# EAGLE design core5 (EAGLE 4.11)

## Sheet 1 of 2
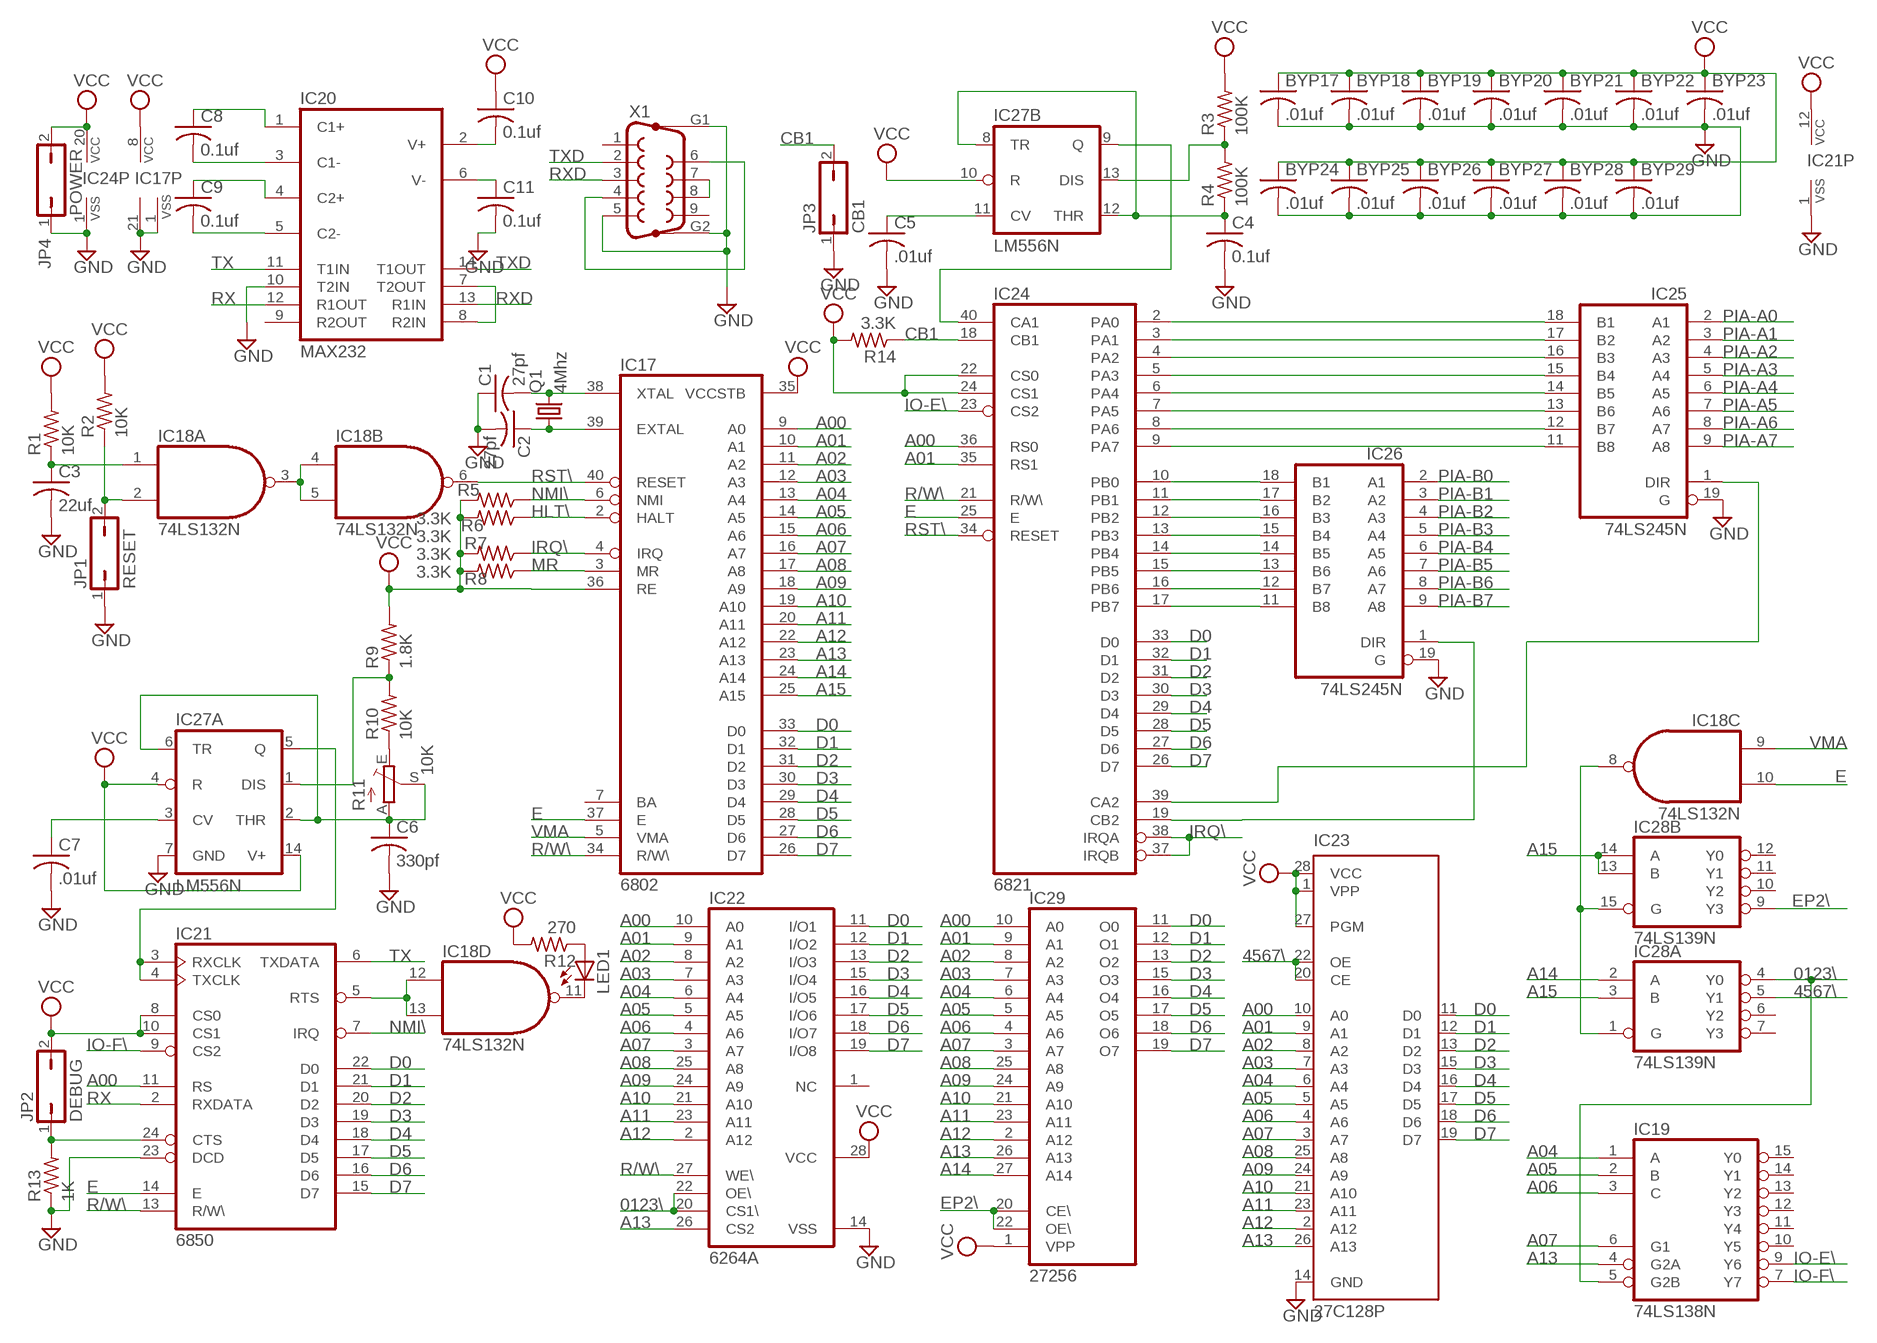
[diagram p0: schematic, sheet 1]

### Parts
BYP17  .01uf  C-US050-025X075  [C050-025X075]
BYP18  .01uf  C-US050-025X075  [C050-025X075]
BYP19  .01uf  C-US050-025X075  [C050-025X075]
BYP20  .01uf  C-US050-025X075  [C050-025X075]
BYP21  .01uf  C-US050-025X075  [C050-025X075]
BYP22  .01uf  C-US050-025X075  [C050-025X075]
BYP23  .01uf  C-US050-025X075  [C050-025X075]
BYP24  .01uf  C-US050-025X075  [C050-025X075]
BYP25  .01uf  C-US050-025X075  [C050-025X075]
BYP26  .01uf  C-US050-025X075  [C050-025X075]
BYP27  .01uf  C-US050-025X075  [C050-025X075]
BYP28  .01uf  C-US050-025X075  [C050-025X075]
BYP29  .01uf  C-US050-025X075  [C050-025X075]
C1  27pf  C-US050-025X075  [C050-025X075]
C2  27pf  C-US050-025X075  [C050-025X075]
C3  22uf  C-US102-043X133  [C102-043X133]
C4  0.1uf  C-US050-025X075  [C050-025X075]
C5  .01uf  C-US050-025X075  [C050-025X075]
C6  330pf  C-US050-025X075  [C050-025X075]
C7  .01uf  C-US050-025X075  [C050-025X075]
C8  0.1uf  C-US050-025X075  [C050-025X075]
C9  0.1uf  C-US050-025X075  [C050-025X075]
C10  0.1uf  C-US050-025X075  [C050-025X075]
C11  0.1uf  C-US050-025X075  [C050-025X075]
IC17  6802  [DIL40]
IC18  74LS132N  74LS00N  [DIL14]
IC19  74LS138N  [DIL16]
IC20  MAX232  [DIL16]
IC21  6850  [DIL24]
IC22  6264A  [DIL28-6]
IC23  27C128P  [DIL28-6]
IC24  6821  [DIL40]
IC25  74LS245N  [DIL20]
IC26  74LS245N  [DIL20]
IC27  LM556N  [DIL14]
IC28  74LS139N  [DIL16]
IC29  27256  [DIL28]
JP1  RESET  JP1Q  [JP1]
JP2  DEBUG  JP1Q  [JP1]
JP3  CB1  JP1Q  [JP1]
JP4  POWER  JP1Q  [JP1]
LED1  LED3MM  [LED3MM]
Q1  4Mhz  CRYTALHC18U-V  [HC18U-V]
R1  10K  R-US_0207/7  [0207/7]
R2  10K  R-US_0207/7  [0207/7]
R3  100K  R-US_0207/7  [0207/7]
R4  100K  R-US_0207/7  [0207/7]
R5  3.3K  R-US_0207/7  [0207/7]
R6  3.3K  R-US_0207/7  [0207/7]
R7  3.3K  R-US_0207/7  [0207/7]
R8  3.3K  R-US_0207/7  [0207/7]
R9  1.8K  R-US_0207/7  [0207/7]
R10  10K  R-US_0207/7  [0207/7]
R11  10K  TRIM_EU-B90P  [SP19L]
R12  270  R-US_0207/7  [0207/7]
R13  1K  R-US_0207/7  [0207/7]
R14  3.3K  R-US_0207/7  [0207/7]
X1  F09HP  [F09HP]

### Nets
0123\: IC19.5(G2B) IC22.20(CS1\) IC22.22(OE\) IC28.4(A:Y0)
4567\: IC23.20(CE) IC23.22(OE) IC28.5(A:Y1)
A00: IC17.9(A0) IC21.11(RS) IC22.10(A0) IC23.10(A0) IC24.36(RS0) IC29.10(A0)
A01: IC17.10(A1) IC22.9(A1) IC23.9(A1) IC24.35(RS1) IC29.9(A1)
A02: IC17.11(A2) IC22.8(A2) IC23.8(A2) IC29.8(A2)
A03: IC17.12(A3) IC22.7(A3) IC23.7(A3) IC29.7(A3)
A04: IC17.13(A4) IC19.1(A) IC22.6(A4) IC23.6(A4) IC29.6(A4)
A05: IC17.14(A5) IC19.2(B) IC22.5(A5) IC23.5(A5) IC29.5(A5)
A06: IC17.15(A6) IC19.3(C) IC22.4(A6) IC23.4(A6) IC29.4(A6)
A07: IC17.16(A7) IC19.6(G1) IC22.3(A7) IC23.3(A7) IC29.3(A7)
A08: IC17.17(A8) IC22.25(A8) IC23.25(A8) IC29.25(A8)
A09: IC17.18(A9) IC22.24(A9) IC23.24(A9) IC29.24(A9)
A10: IC17.19(A10) IC22.21(A10) IC23.21(A10) IC29.21(A10)
A11: IC17.20(A11) IC22.23(A11) IC23.23(A11) IC29.23(A11)
A12: IC17.22(A12) IC22.2(A12) IC23.2(A12) IC29.2(A12)
A13: IC17.23(A13) IC19.4(G2A) IC22.26(CS2) IC23.26(A13) IC29.26(A13)
A14: IC17.24(A14) IC28.2(A:A) IC29.27(A14)
A15: IC17.25(A15) IC28.3(A:B) IC28.13(B:B) IC28.14(B:A)
CB1: IC24.18(CB1) JP3.2 R14.1
D0: IC17.33(D0) IC21.22(D0) IC22.11(I/O1) IC23.11(D0) IC24.33(D0) IC29.11(O0)
D1: IC17.32(D1) IC21.21(D1) IC22.12(I/O2) IC23.12(D1) IC24.32(D1) IC29.12(O1)
D2: IC17.31(D2) IC21.20(D2) IC22.13(I/O3) IC23.13(D2) IC24.31(D2) IC29.13(O2)
D3: IC17.30(D3) IC21.19(D3) IC22.15(I/O4) IC23.15(D3) IC24.30(D3) IC29.15(O3)
D4: IC17.29(D4) IC21.18(D4) IC22.16(I/O5) IC23.16(D4) IC24.29(D4) IC29.16(O4)
D5: IC17.28(D5) IC21.17(D5) IC22.17(I/O6) IC23.17(D5) IC24.28(D5) IC29.17(O5)
D6: IC17.27(D6) IC21.16(D6) IC22.18(I/O7) IC23.18(D6) IC24.27(D6) IC29.18(O6)
D7: IC17.26(D7) IC21.15(D7) IC22.19(I/O8) IC23.19(D7) IC24.26(D7) IC29.19(O7)
E: IC17.37(E) IC18.10(C:I1) IC21.14(E) IC24.25(E)
EP2\: IC28.9(B:Y3) IC29.20(CE\) IC29.22(OE\)
GND [Power]: BYP17.2 BYP18.2 BYP19.2 BYP20.2 BYP21.2 BYP22.2 BYP23.2 BYP24.2 BYP25.2 BYP26.2 BYP27.2 BYP28.2 BYP29.2 C1.1 C2.2 C3.2 C4.2 C5.2 C6.2 C7.2 C11.2 IC17.1(VSS) IC17.21(VSS) IC20.10(T2IN) IC21.1(VSS) IC21.23(DCD) IC22.14(VSS) IC23.14(GND) IC24.1(VSS) IC25.19(G) IC26.19(G) IC27.7(A:GND) JP1.1 JP3.1 JP4.1 R13.1 X1.5 X1.G1 X1.G2 ; also sheet 2
HLT\: IC17.2(HALT) R5.1
IO-E\: IC19.9(Y6) IC24.23(CS2)
IO-F\: IC19.7(Y7) IC21.9(CS2)
IRQ\: IC17.4(IRQ) IC24.37(IRQB) IC24.38(IRQA) R7.1
MR: IC17.3(MR) R8.1
N$3: C2.1 IC17.39(EXTAL) Q1.1
N$4: C1.2 IC17.38(XTAL) Q1.2
N$5: IC24.2(PA0) IC25.18(B1)
N$6: IC18.3(A:O) IC18.4(B:I0) IC18.5(B:I1)
N$21: C3.1 IC18.1(A:I0) R1.1
N$22: IC18.2(A:I1) JP1.2 R2.1
N$23: IC21.3(RXCLK) IC21.4(TXCLK) IC27.5(A:Q)
N$24: IC24.10(PB0) IC26.18(B1)
N$25: IC24.11(PB1) IC26.17(B2)
N$27: C6.1 IC27.2(A:THR) IC27.6(A:TR) R11.A R11.S
N$28: IC27.1(A:DIS) R9.1 R10.2
N$94: IC24.12(PB2) IC26.16(B3)
N$124: IC24.13(PB3) IC26.15(B4)
N$125: IC24.14(PB4) IC26.14(B5)
N$126: IC24.15(PB5) IC26.13(B6)
N$127: IC24.16(PB6) IC26.12(B7)
N$128: IC24.17(PB7) IC26.11(B8)
N$129: IC24.3(PA1) IC25.17(B2)
N$130: IC24.4(PA2) IC25.16(B3)
N$131: IC24.5(PA3) IC25.15(B4)
N$132: IC24.6(PA4) IC25.14(B5)
N$133: IC24.7(PA5) IC25.13(B6)
N$134: IC24.8(PA6) IC25.12(B7)
N$135: IC24.9(PA7) IC25.11(B8)
N$136: IC24.19(CB2) IC26.1(DIR)
N$137: IC24.39(CA2) IC25.1(DIR)
N$138: IC24.40(CA1) IC27.9(B:Q)
N$140: C4.1 IC27.8(B:TR) IC27.12(B:THR) R4.1
N$141: IC27.13(B:DIS) R3.1 R4.2
N$142: C5.1 IC27.11(B:CV)
N$143: R10.1 R11.E
N$144: X1.4 X1.6
N$145: X1.7 X1.8
N$147: IC18.12(D:I0) IC18.13(D:I1) IC21.5(RTS)
N$148: IC18.11(D:O) LED1.K(C)
N$149: LED1.A R12.1
N$150: IC21.24(CTS) JP2.1 R13.2
N$151: IC18.8(C:O) IC28.1(A:G) IC28.15(B:G)
N$153: IC20.7(T2OUT) IC20.8(R2IN)
N$154: C7.1 IC27.3(A:CV)
N$155: C9.2 IC20.5(C2-)
N$156: C9.1 IC20.4(C2+)
N$157: C8.2 IC20.3(C1-)
N$158: C8.1 IC20.1(C1+)
N$159: C11.1 IC20.6(V-)
N$160: C10.2 IC20.2(V+)
NMI\: IC17.6(NMI) IC21.7(IRQ) R6.1
PIA-A0: IC25.2(A1) ; also sheet 2
PIA-A1: IC25.3(A2) ; also sheet 2
PIA-A2: IC25.4(A3) ; also sheet 2
PIA-A3: IC25.5(A4) ; also sheet 2
PIA-A4: IC25.6(A5) ; also sheet 2
PIA-A5: IC25.7(A6) ; also sheet 2
PIA-A6: IC25.8(A7) ; also sheet 2
PIA-A7: IC25.9(A8) ; also sheet 2
PIA-B0: IC26.2(A1) ; also sheet 2
PIA-B1: IC26.3(A2) ; also sheet 2
PIA-B2: IC26.4(A3) ; also sheet 2
PIA-B3: IC26.5(A4) ; also sheet 2
PIA-B4: IC26.6(A5) ; also sheet 2
PIA-B5: IC26.7(A6) ; also sheet 2
PIA-B6: IC26.8(A7) ; also sheet 2
PIA-B7: IC26.9(A8) ; also sheet 2
R/W\: IC17.34(R/W\) IC21.13(R/W\) IC22.27(WE\) IC24.21(R/W\)
RST\: IC17.40(RESET) IC18.6(B:O) IC24.34(RESET)
RX: IC20.12(R1OUT) IC21.2(RXDATA)
RXD: IC20.13(R1IN) X1.3
TX: IC20.11(T1IN) IC21.6(TXDATA)
TXD: IC20.14(T1OUT) X1.2
VCC [Power]: BYP17.1 BYP18.1 BYP19.1 BYP20.1 BYP21.1 BYP22.1 BYP23.1 BYP24.1 BYP25.1 BYP26.1 BYP27.1 BYP28.1 BYP29.1 C10.1 IC17.8(VCC) IC17.35(VCCSTB) IC17.36(RE) IC21.8(CS0) IC21.10(CS1) IC21.12(VCC) IC22.28(VCC) IC23.1(VPP) IC23.27(PGM) IC23.28(VCC) IC24.20(VCC) IC24.22(CS0) IC24.24(CS1) IC27.4(A:R) IC27.10(B:R) IC27.14(A:V+) IC29.1(VPP) JP2.2 JP4.2 R1.2 R2.2 R3.2 R5.2 R6.2 R7.2 R8.2 R9.2 R12.2 R14.2 ; also sheet 2
VMA: IC17.5(VMA) IC18.9(C:I0)
Unconnected: IC17.7(BA) IC19.10(Y5) IC19.11(Y4) IC19.12(Y3) IC19.13(Y2) IC19.14(Y1) IC19.15(Y0) IC20.9(R2OUT) IC22.1(NC) IC28.6(A:Y2) IC28.7(A:Y3) IC28.10(B:Y2) IC28.11(B:Y1) IC28.12(B:Y0) X1.1 X1.9

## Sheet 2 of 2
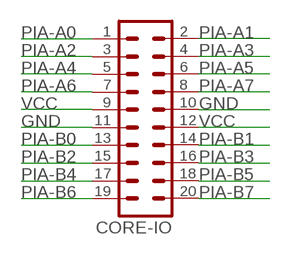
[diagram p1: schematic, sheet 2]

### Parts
CORE-IO  MA10-2  [MA10-2]

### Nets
GND [Power]: CORE-IO.10 CORE-IO.11 ; also sheet 1
PIA-A0: CORE-IO.1 ; also sheet 1
PIA-A1: CORE-IO.2 ; also sheet 1
PIA-A2: CORE-IO.3 ; also sheet 1
PIA-A3: CORE-IO.4 ; also sheet 1
PIA-A4: CORE-IO.5 ; also sheet 1
PIA-A5: CORE-IO.6 ; also sheet 1
PIA-A6: CORE-IO.7 ; also sheet 1
PIA-A7: CORE-IO.8 ; also sheet 1
PIA-B0: CORE-IO.13 ; also sheet 1
PIA-B1: CORE-IO.14 ; also sheet 1
PIA-B2: CORE-IO.15 ; also sheet 1
PIA-B3: CORE-IO.16 ; also sheet 1
PIA-B4: CORE-IO.17 ; also sheet 1
PIA-B5: CORE-IO.18 ; also sheet 1
PIA-B6: CORE-IO.19 ; also sheet 1
PIA-B7: CORE-IO.20 ; also sheet 1
VCC [Power]: CORE-IO.9 CORE-IO.12 ; also sheet 1

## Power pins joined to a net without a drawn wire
GND: IC18.7(P:GND) IC19.8(GND) IC20.15(GND) IC25.10(GND) IC26.10(GND) IC28.8(P:GND) IC29.14(GND)
VCC: IC18.14(P:VCC) IC19.16(VCC) IC20.16(VCC) IC25.20(VCC) IC26.20(VCC) IC28.16(P:VCC) IC29.28(VCC)

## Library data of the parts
BYP17-BYP29 C1-C11 = rcl:C-US: CAPACITOR, American symbol
CORE-IO = con-lstb:MA10-2: PIN HEADER
IC17 = micro-motorola:6802: MICROCONTROLLER/MEMORY DEVICE
IC18 = 74xx-us:74*00: Quad 2-input NAND gate
IC19 = 74xx-us:74*138: 3-line to 8-line DECODER/DEMULTIPLEXER
IC20 = maxim:MAX232: RS232 TRANSEIVER
IC21 = micro-motorola:6850: MICROCONTROLLER/MEMORY DEVICE
IC22 = memory-hitachi:6264A: MEMORY
IC23 = microchip:27*128: CMOS EPROM 128 K (16 K x 8)
IC24 = micro-motorola:6821: MICROCONTROLLER/MEMORY DEVICE
IC25 IC26 = 74xx-us:74*245: Octal BUS TRANSCEIVER, 3-state
IC27 = linear:*556: Dual TIMER
IC28 = 74xx-us:74*139: Dual 2-line to 4-line DECODER/DEMULTIPLEXER
IC29 = memory:27256: MEMORY
JP1-JP4 = jumper:JP1Q: JUMPER
LED1 = led:LED: LED
Q1 = crystal:CRYTAL: CRYSTAL
R1-R10 R12-R14 = rcl:R-US_: RESISTOR, American symbol
R11 = pot:TRIM_EU-: POTENTIOMETER
X1 = con-subd:F09HP: SUB-D

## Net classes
1 Power: width 0.508 mm, drill 0.254 mm, clearance 0.254 mm

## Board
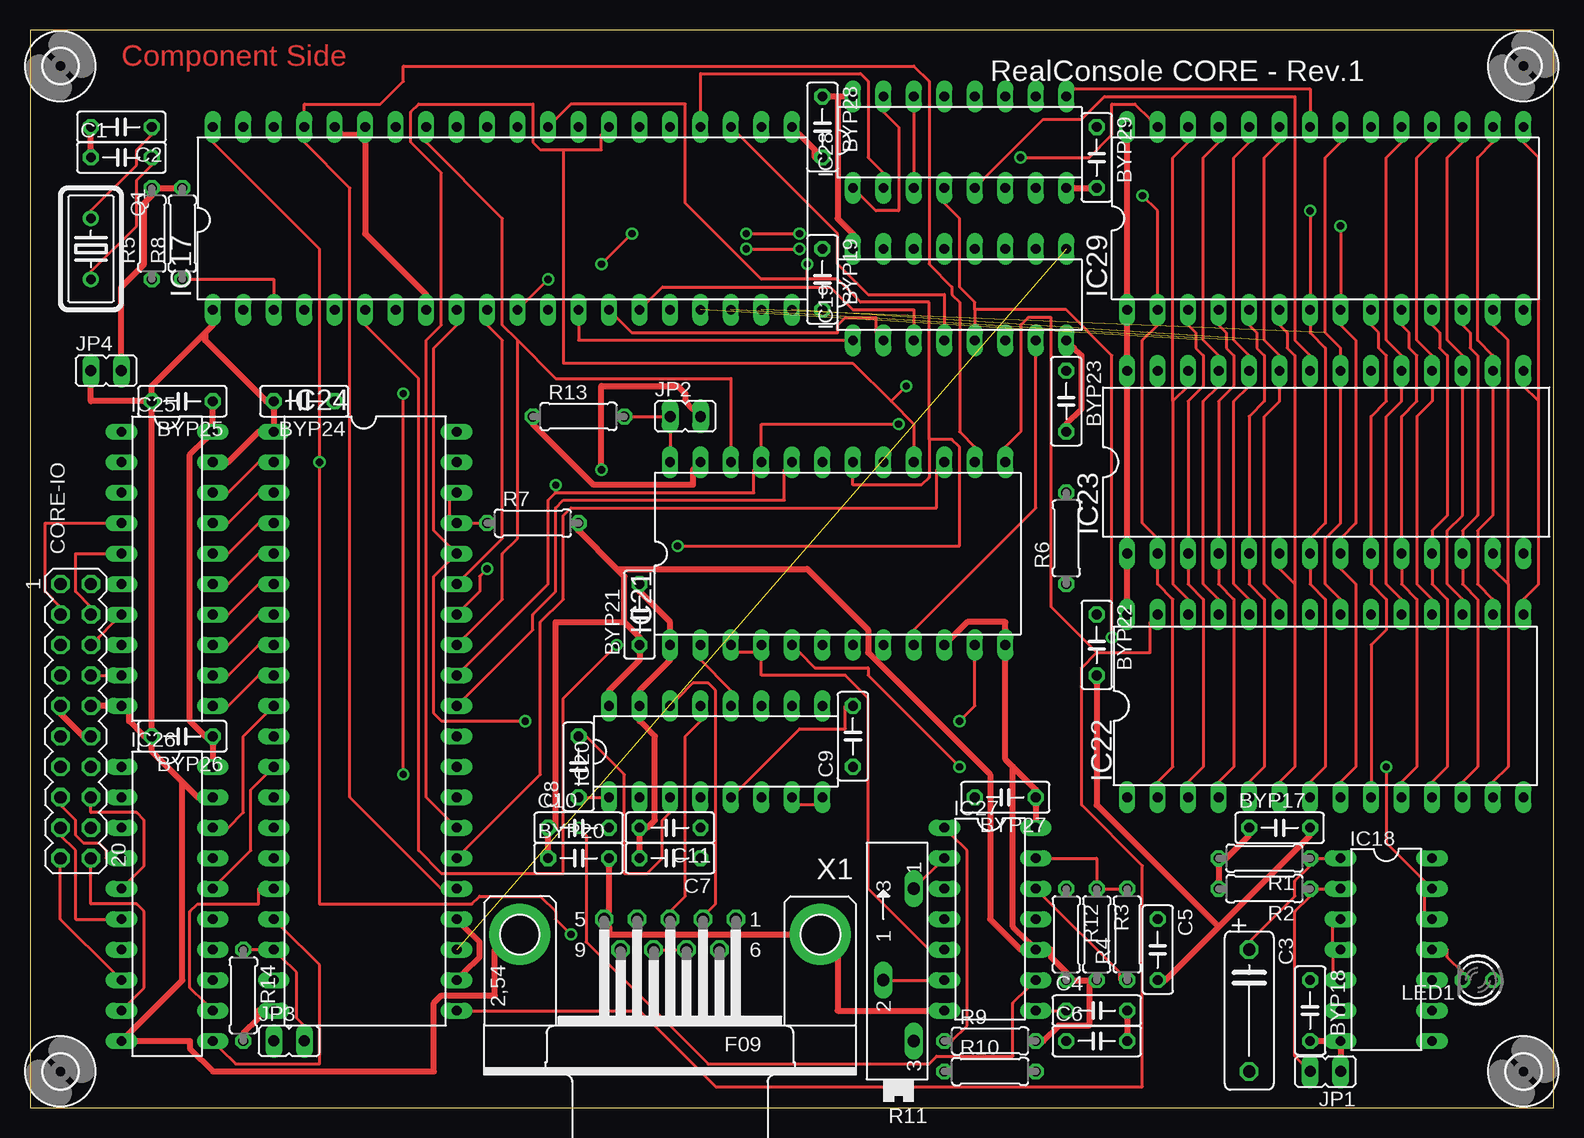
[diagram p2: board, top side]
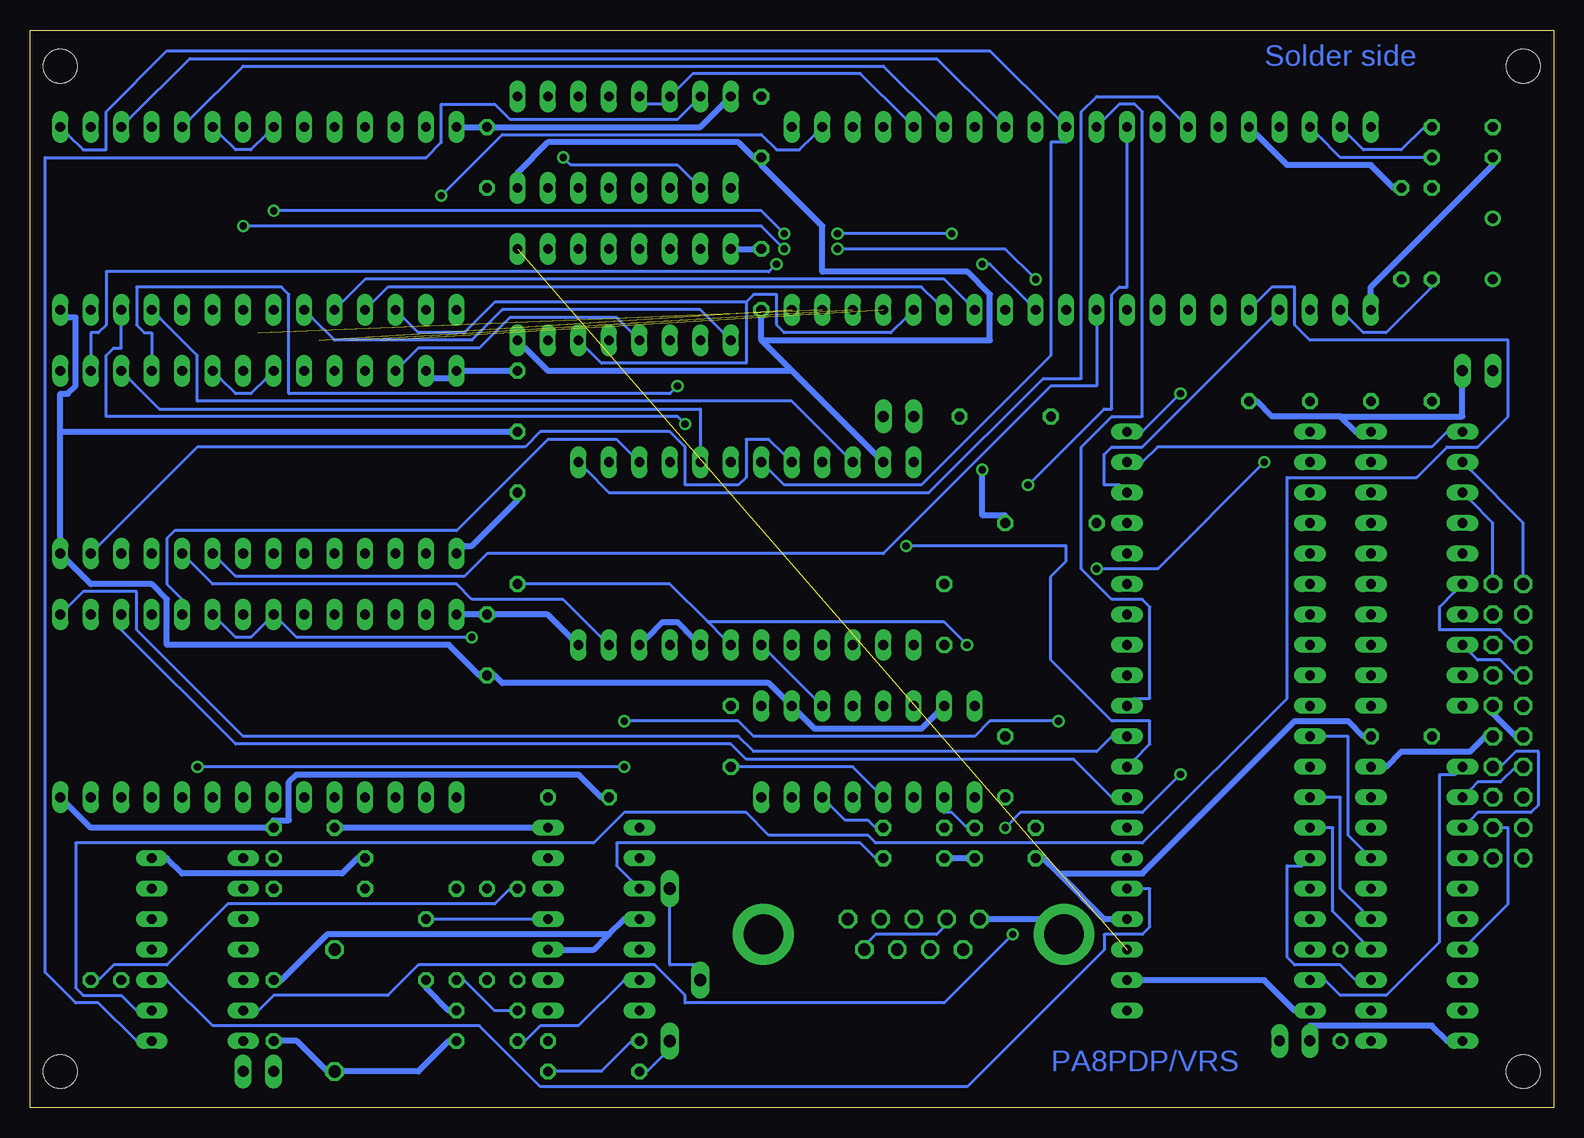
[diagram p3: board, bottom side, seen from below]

Size 126.98 x 89.84 mm. Coordinates in mm from the lower left corner, seen from the top.
Outline: 0,0 126.98,0 126.98,89.84 0,89.84 0,0
Copper layers (1*16): Top 0.035mm / dielectric 1.5mm / Bottom 0.035mm
Design rules "olimex10mil": minimum track width 10mil, minimum drill 24mil, track to track 10mil, track to pad 10mil, pad to pad 10mil, via to via 10mil, smd to smd 10mil, copper to edge 40mil, drill to drill 10mil, minimum pad ring 10mil, minimum via ring 8mil, stop-mask expansion 0mil, vias tented up to drill 0mil, thermal gap 10mil

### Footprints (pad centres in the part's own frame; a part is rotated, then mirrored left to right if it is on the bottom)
C050-025X075 = drill 0.813 octagon: 1 -2.54,0; 2 2.54,0
C102-043X133 = drill 1.016 octagon: 1 -5.08,0; 2 5.08,0
MA10-2 = drill 1.016 octagon: 1 -11.43,-1.27; 2 -11.43,1.27; 3 -8.89,-1.27; 4 -8.89,1.27; 5 -6.35,-1.27; 6 -6.35,1.27; 7 -3.81,-1.27; 8 -3.81,1.27; 9 -1.27,-1.27; 10 -1.27,1.27; 11 1.27,-1.27; 12 1.27,1.27; 13 3.81,-1.27; 14 3.81,1.27; 15 6.35,-1.27; 16 6.35,1.27; 17 8.89,-1.27; 18 8.89,1.27; 19 11.43,-1.27; 20 11.43,1.27
DIL40 = drill 0.813 long: 1 -24.13,-7.62; 2 -21.59,-7.62; 3 -19.05,-7.62; 4 -16.51,-7.62; 5 -13.97,-7.62; 6 -11.43,-7.62; 7 -8.89,-7.62; 8 -6.35,-7.62; 9 -3.81,-7.62; 10 -1.27,-7.62; 11 1.27,-7.62; 12 3.81,-7.62; 13 6.35,-7.62; 14 8.89,-7.62; 15 11.43,-7.62; 16 13.97,-7.62; 17 16.51,-7.62; 18 19.05,-7.62; 19 21.59,-7.62; 20 24.13,-7.62; 21 24.13,7.62; 22 21.59,7.62; 23 19.05,7.62; 24 16.51,7.62; 25 13.97,7.62; 26 11.43,7.62; 27 8.89,7.62; 28 6.35,7.62; 29 3.81,7.62; 30 1.27,7.62; 31 -1.27,7.62; 32 -3.81,7.62; 33 -6.35,7.62; 34 -8.89,7.62; 35 -11.43,7.62; 36 -13.97,7.62; 37 -16.51,7.62; 38 -19.05,7.62; 39 -21.59,7.62; 40 -24.13,7.62
DIL14 = drill 0.813 long: 1 -7.62,-3.81; 2 -5.08,-3.81; 3 -2.54,-3.81; 4 0,-3.81; 5 2.54,-3.81; 6 5.08,-3.81; 7 7.62,-3.81; 8 7.62,3.81; 9 5.08,3.81; 10 2.54,3.81; 11 0,3.81; 12 -2.54,3.81; 13 -5.08,3.81; 14 -7.62,3.81
DIL16 = drill 0.813 long: 1 -8.89,-3.81; 2 -6.35,-3.81; 3 -3.81,-3.81; 4 -1.27,-3.81; 5 1.27,-3.81; 6 3.81,-3.81; 7 6.35,-3.81; 8 8.89,-3.81; 9 8.89,3.81; 10 6.35,3.81; 11 3.81,3.81; 12 1.27,3.81; 13 -1.27,3.81; 14 -3.81,3.81; 15 -6.35,3.81; 16 -8.89,3.81
DIL24 = drill 0.813 long: 1 -13.97,-7.62; 2 -11.43,-7.62; 3 -8.89,-7.62; 4 -6.35,-7.62; 5 -3.81,-7.62; 6 -1.27,-7.62; 7 1.27,-7.62; 8 3.81,-7.62; 9 6.35,-7.62; 10 8.89,-7.62; 11 11.43,-7.62; 12 13.97,-7.62; 13 13.97,7.62; 14 11.43,7.62; 15 8.89,7.62; 16 6.35,7.62; 17 3.81,7.62; 18 1.27,7.62; 19 -1.27,7.62; 20 -3.81,7.62; 21 -6.35,7.62; 22 -8.89,7.62; 23 -11.43,7.62; 24 -13.97,7.62
DIL28-6 = drill 0.813 long: 1 -16.51,-7.62; 2 -13.97,-7.62; 3 -11.43,-7.62; 4 -8.89,-7.62; 5 -6.35,-7.62; 6 -3.81,-7.62; 7 -1.27,-7.62; 8 1.27,-7.62; 9 3.81,-7.62; 10 6.35,-7.62; 11 8.89,-7.62; 12 11.43,-7.62; 13 13.97,-7.62; 14 16.51,-7.62; 15 16.51,7.62; 16 13.97,7.62; 17 11.43,7.62; 18 8.89,7.62; 19 6.35,7.62; 20 3.81,7.62; 21 1.27,7.62; 22 -1.27,7.62; 23 -3.81,7.62; 24 -6.35,7.62; 25 -8.89,7.62; 26 -11.43,7.62; 27 -13.97,7.62; 28 -16.51,7.62
DIL20 = drill 0.813 long: 1 -11.43,-3.81; 2 -8.89,-3.81; 3 -6.35,-3.81; 4 -3.81,-3.81; 5 -1.27,-3.81; 6 1.27,-3.81; 7 3.81,-3.81; 8 6.35,-3.81; 9 8.89,-3.81; 10 11.43,-3.81; 11 11.43,3.81; 12 8.89,3.81; 13 6.35,3.81; 14 3.81,3.81; 15 1.27,3.81; 16 -1.27,3.81; 17 -3.81,3.81; 18 -6.35,3.81; 19 -8.89,3.81; 20 -11.43,3.81
DIL28 = drill 0.813 long: 1 -16.51,-7.62; 2 -13.97,-7.62; 3 -11.43,-7.62; 4 -8.89,-7.62; 5 -6.35,-7.62; 6 -3.81,-7.62; 7 -1.27,-7.62; 8 1.27,-7.62; 9 3.81,-7.62; 10 6.35,-7.62; 11 8.89,-7.62; 12 11.43,-7.62; 13 13.97,-7.62; 14 16.51,-7.62; 15 16.51,7.62; 16 13.97,7.62; 17 11.43,7.62; 18 8.89,7.62; 19 6.35,7.62; 20 3.81,7.62; 21 1.27,7.62; 22 -1.27,7.62; 23 -3.81,7.62; 24 -6.35,7.62; 25 -8.89,7.62; 26 -11.43,7.62; 27 -13.97,7.62; 28 -16.51,7.62
JP1 = drill 0.914 long: 1 0,-1.27; 2 0,1.27
LED3MM = drill 0.813 octagon: A -1.27,0; K 1.27,0
HC18U-V = drill 0.813 round: 1 -2.54,0; 2 2.54,0
0207/7 = drill 0.813 octagon: 1 -3.81,0; 2 3.81,0
SP19L = drill 1.016 long: A 5.715,-1.27; E -6.985,-1.27; S -1.905,1.27
2,8 = hole 2.8: 0,0
F09HP = drill 1.016 octagon: 1 -5.486,-1.27; 2 -2.743,-1.27; 3 0,-1.27; 4 2.743,-1.27; 5 5.486,-1.27; 6 -4.115,1.27; 7 -1.372,1.27; 8 1.372,1.27; 9 4.115,1.27 | drill 3.302 pad 5.08 round: G1 -12.522,0; G2 12.522,0

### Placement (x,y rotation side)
BYP17  104.14,23.33 0 top
BYP18  106.68,8.09 270 top
BYP19  66.04,69.05 270 top
BYP20  45.71,20.79 0 top
BYP21  50.79,41.11 90 top
BYP22  88.9,38.57 270 top
BYP23  86.36,58.89 270 top
BYP24  22.86,58.89 180 top
BYP25  12.69,58.89 180 top
BYP26  12.69,30.95 180 top
BYP27  81.28,25.87 180 top
BYP28  66.04,81.75 270 top
BYP29  88.9,79.21 270 top
C1  7.62,79.21 0 top
C2  7.62,81.75 180 top
C3  101.59,8.09 270 top
C4  88.9,8.09 0 top
C5  93.98,13.17 270 top
C6  88.9,5.55 0 top
C7  53.34,20.79 180 top
C8  45.71,28.41 90 top
C9  68.58,30.95 90 top
C10  45.71,23.33 0 top
C11  53.34,23.33 180 top
CORE-IO  3.81,32.22 270 top
IC17  39.36,74.13 0 top
IC18  113.03,13.17 270 top
IC19  77.47,67.78 0 top
IC20  57.14,29.68 0 top
IC21  67.31,46.19 0 top
IC22  107.95,33.49 0 top
IC23  107.95,53.81 0 top
IC24  27.94,32.22 270 top
IC25  11.42,44.92 270 top
IC26  11.42,16.98 270 top
IC27  80.01,15.71 270 top
IC28  77.47,80.48 0 top
IC29  107.95,74.13 0 top
JP1  107.95,3.01 90 top
JP2  54.6,57.62 270 top
JP3  21.59,5.55 270 top
JP4  6.34,61.43 270 top
LED1  120.65,10.63 180 top
Q1  5.08,71.59 270 top
R1  102.87,20.79 180 top
R2  102.87,18.25 180 top
R3  88.9,14.44 270 top
R4  91.44,14.44 90 top
R5  10.15,72.86 90 top
R6  86.36,47.46 90 top
R7  41.9,48.73 0 top
R8  12.69,72.86 90 top
R9  80.01,5.55 0 top
R10  80.01,3.01 0 top
R11  72.39,12.54 90 top
R12  86.36,14.44 270 top
R13  45.71,57.62 0 top
R14  17.78,9.36 270 top
U$3  [2,8]  2.54,86.83 0 top
U$4  [2,8]  2.54,3.01 0 top
U$5  [2,8]  124.45,86.83 0 top
U$6  [2,8]  124.45,3.01 0 top
X1  53.34,14.44 180 top

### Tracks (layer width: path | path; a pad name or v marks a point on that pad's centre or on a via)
0123\  (via drill 0.61)
  Top 0.254: 78.73,66.51 78.73,65.24 IC19.5 | 78.73,66.51 78.73,67.14 77.47,68.41 77.47,74.13 76.2,75.4 IC28.4 | v90.17,39.2 90.17,62.7 86.36,66.51 78.73,66.51
  Bottom 0.254: IC22.20 111.12,40.48 109.85,39.2 108.58,39.2 107.31,40.48 IC22.22 106.04,40.48 104.77,39.2 v90.17,39.2
4567\
  Top 0.254: IC28.5 79.37,77.3 84.45,82.39 87.62,82.39 89.53,84.29 105.41,84.29 105.41,63.97 106.68,62.7 IC23.22
  Bottom 0.254: IC23.22 107.31,60.8 108.58,59.52 109.85,59.52 111.12,60.8 IC23.20
A00  (via drill 0.61)
  Top 0.254: IC17.9 35.55,65.24 33.65,63.34 33.65,48.09 34.92,46.82 IC24.36 34.92,45.55 33.65,44.28 33.65,32.85 34.28,32.22 v41.27,32.22 | IC22.10 114.3,27.14 115.56,28.41 115.56,42.38 114.3,43.65 114.3,44.92 IC23.10 114.3,47.46 114.3,57.62 115.56,58.89 115.56,62.7 114.93,63.34 114.93,64.61 114.3,65.24 IC29.10 | v77.47,32.22 78.73,33.49 78.73,37.3 IC21.11
  Bottom 0.254: IC21.11 79.37,39.2 82.55,42.38 90.17,42.38 91.44,43.65 111.76,43.65 113.66,45.55 IC23.10 | v41.27,32.22 46.98,32.22 48.25,30.95 66.67,30.95 67.94,32.22 v77.47,32.22
A01
  Top 0.254: IC24.35 36.19,44.28 39.36,47.46 39.36,63.97 38.09,65.24 IC17.10 | IC22.9 111.76,27.14 111.76,38.57 113.03,39.84 113.03,42.38 111.76,43.65 111.76,44.92 IC23.9 111.76,47.46 111.76,57.62 113.03,58.89 113.03,62.7 112.39,63.34 112.39,64.61 111.76,65.24 IC29.9
  Bottom 0.254: IC17.10 38.09,65.24 38.09,60.16 41.9,60.16 55.88,46.19 88.9,46.19 90.8,44.28 109.85,44.28 111.12,45.55 IC23.9
A02  (via drill 0.61)
  Top 0.254: IC22.8 109.22,27.14 110.48,28.41 110.48,43.65 109.22,44.92 IC23.8 109.22,47.46 110.48,48.73 110.48,63.97 109.22,65.24 IC29.8 109.22,67.78 v109.22,73.5 | v43.17,69.05 41.27,67.14 IC17.11 | v59.68,71.59 v64.13,71.59
  Bottom 0.254: v43.17,69.05 45.71,71.59 v59.68,71.59 | v64.13,71.59 66.04,73.5 v109.22,73.5
A03  (via drill 0.61)
  Top 0.254: IC22.7 106.68,27.14 107.95,28.41 107.95,42.38 106.68,43.65 106.68,44.92 IC23.7 106.68,47.46 107.95,48.73 107.95,63.34 106.68,64.61 106.68,65.24 IC29.7 106.68,67.78 v106.68,74.77 | v47.62,70.32 v50.16,72.86 | v59.68,72.86 v64.13,72.86
  Bottom 0.254: v47.62,70.32 46.98,70.32 43.81,67.14 IC17.12 | v50.16,72.86 v59.68,72.86 | v64.13,72.86 66.04,74.77 v106.68,74.77
A04
  Top 0.254: IC19.1 67.94,63.97 45.71,63.97 45.71,65.24 IC17.13 | 105.41,43.65 105.41,28.41 104.14,27.14 IC22.6 | 105.41,43.65 104.14,44.92 IC23.6 | 105.41,43.65 105.41,62.7 104.77,63.34 104.77,64.61 104.14,65.24 IC29.6
  Bottom 0.254: IC19.1 69.21,64.61 71.12,66.51 87.62,66.51 90.17,63.97 101.59,63.97 103.5,65.88 IC29.6
A05
  Top 0.254: IC17.14 48.89,65.88 50.16,64.61 67.31,64.61 67.31,65.24 67.94,65.88 70.48,65.88 70.48,64.61 IC19.2 | IC22.5 101.59,27.14 102.87,28.41 102.87,42.38 101.59,43.65 101.59,44.92 IC23.5 101.59,47.46 101.59,57.62 102.87,58.89 102.87,62.7 102.23,63.34 102.23,64.61 101.59,65.24 IC29.5
  Bottom 0.254: IC17.14 48.89,67.14 50.79,69.05 99.06,69.05 100.96,67.14 IC29.5
A06
  Top 0.254: IC17.15 51.43,67.14 52.7,68.41 66.67,68.41 68.58,66.51 73.66,66.51 73.66,65.24 IC19.3 | IC22.4 99.06,27.14 100.33,28.41 100.33,42.38 99.06,43.65 99.06,44.92 IC23.4 99.06,47.46 99.06,58.89 100.33,60.16 100.33,62.7 99.69,63.34 99.69,64.61 99.06,65.24 IC29.4
  Bottom 0.254: IC17.15 51.43,67.14 52.7,68.41 97.15,68.41 98.42,67.14 IC29.4
A07
  Top 0.254: IC22.3 96.52,27.14 97.79,28.41 97.79,42.38 96.52,43.65 96.52,44.92 IC23.3 96.52,47.46 96.52,58.89 97.79,60.16 97.79,62.7 97.15,63.34 97.15,64.61 96.52,65.24 IC29.3
  Bottom 0.254: 67.31,67.14 66.67,67.78 64.77,67.78 64.77,65.24 64.13,64.61 55.24,64.61 53.97,65.88 IC17.16 | 67.31,67.14 67.31,62.06 79.37,62.06 80.64,63.34 IC19.6 | 67.31,67.14 88.26,67.14 90.8,64.61 94.61,64.61 95.88,65.88 IC29.3
A08  (1 unrouted)
  Top 0.254: IC22.25 99.06,42.38 97.79,43.65 97.79,58.89 99.06,60.16 IC23.25 99.06,62.7 97.79,63.97 97.79,79.21 99.06,80.48 IC29.25
A09  (1 unrouted)
  Top 0.254: IC22.24 101.59,42.38 100.33,43.65 100.33,58.89 101.59,60.16 IC23.24 101.59,62.7 100.33,63.97 100.33,79.21 101.59,80.48 IC29.24
A10  (1 unrouted)
  Top 0.254: IC22.21 109.22,42.38 107.95,43.65 107.95,47.46 109.22,48.73 109.22,60.16 IC23.21 109.22,62.7 109.22,63.34 107.95,64.61 107.95,79.21 109.22,80.48 IC29.21
A11  (1 unrouted)
  Top 0.254: IC22.23 104.14,42.38 102.87,43.65 102.87,57.62 104.14,58.89 104.14,60.16 IC23.23 104.14,62.7 102.87,63.97 102.87,79.21 104.14,80.48 IC29.23
A12  (via drill 0.61)
  Top 0.254: IC22.2 93.98,27.14 95.25,28.41 95.25,42.38 93.98,43.65 93.98,44.92 IC23.2 93.98,47.46 92.7,48.73 92.7,63.97 93.98,65.24 IC29.2 93.98,67.78 93.98,74.77 v92.7,76.03
  Bottom 0.254: v92.7,76.03 87.62,81.11 66.04,81.11 64.77,79.84 62.86,79.84 61.59,81.11 IC17.22
A13
  Top 0.254: 95.25,58.89 95.25,43.65 96.52,42.38 IC22.26 | 95.25,58.89 96.52,60.16 IC23.26 | IC17.23 59.05,81.11 67.31,72.86 67.31,70.32 69.84,67.78 76.2,67.78 76.2,65.24 IC19.4 | 95.25,58.89 95.25,79.21 96.52,80.48 IC29.26
  Bottom 0.254: IC19.4 76.83,64.61 78.1,65.88 86.99,65.88 89.53,63.34 94.61,63.34 95.88,62.06 IC23.26
A14  (via drill 0.61)
  Top 0.254: IC28.2 71.12,77.94 69.84,79.21 69.84,85.56 69.21,86.19 55.88,86.19 55.88,83.02 IC17.24 | v82.55,79.21 88.26,79.21 90.17,81.11 90.17,83.66 92.07,83.66 93.34,82.39 IC29.27
  Bottom 0.254: v82.55,79.21 81.91,78.58 73.02,78.58 71.75,77.3 IC28.2
A15
  Top 0.254: IC28.3 73.66,77.94 73.66,83.02 IC28.14
  Bottom 0.254: IC17.25 53.97,82.39 57.78,86.19 71.75,86.19 73.02,84.92 IC28.14 74.29,83.66 75.56,83.66 IC28.13
CB1
  Top 0.254: R14.1 18.41,13.17 19.05,13.17 IC24.18 20.95,12.54 22.22,11.27 22.22,7.46 22.86,6.82 JP3.2
D0
  Top 0.254: IC22.11 116.84,27.14 118.11,28.41 118.11,42.38 116.84,43.65 116.84,44.92 IC23.11 116.84,47.46 116.84,48.09 118.11,49.37 118.11,62.7 117.47,63.34 117.47,64.61 116.84,65.24 IC29.11 | 40.63,63.97 43.81,60.8 58.41,60.8 58.41,55.08 IC21.22 | 40.63,63.97 39.36,65.24 39.36,74.13 33.02,80.48 IC17.33 | 40.63,63.97 40.63,47.46 39.36,46.19 39.36,42.38 36.19,39.2 IC24.33
  Bottom 0.254: IC29.11 116.2,65.88 113.03,62.7 113.03,58.89 63.49,58.89 59.05,54.45 IC21.22
D1  (via drill 0.61)
  Top 0.254: IC22.12 119.38,27.14 120.65,28.41 120.65,42.38 119.38,43.65 119.38,44.92 IC23.12 119.38,47.46 119.38,48.09 120.65,49.37 120.65,62.7 120.01,63.34 120.01,64.61 119.38,65.24 IC29.12 | 43.81,51.27 43.17,50.63 43.17,43.65 36.19,36.66 IC24.32 | 43.81,51.27 60.32,51.27 60.32,53.17 IC21.21 60.95,55.08 60.95,56.98 v72.39,56.98 | 43.81,51.27 v43.81,51.91
  Bottom 0.254: v43.81,51.91 37.46,58.25 36.82,58.25 36.82,67.78 36.19,68.41 35.55,68.41 35.55,80.48 IC17.32 | v72.39,56.98 73.02,57.62 120.65,57.62 120.65,62.7 120.01,63.34 119.38,63.34 119.38,65.24 IC29.12
D2
  Top 0.254: 123.19,43.65 123.19,28.41 121.92,27.14 IC22.13 | 123.19,43.65 121.92,44.92 IC23.13 | 123.19,43.65 123.19,63.97 121.92,65.24 IC29.13 | IC24.31 36.19,34.12 41.9,39.84 41.9,41.11 43.81,43.02 43.81,50 44.45,50.63 62.86,50.63 62.86,53.17 IC21.20
  Bottom 0.254: IC17.31 37.46,82.39 36.19,83.66 34.92,83.66 34.28,83.02 34.28,57.62 36.82,57.62 39.36,55.08 39.36,44.92 36.82,42.38 34.28,42.38 33.65,41.74 33.65,34.12 34.92,34.12 IC24.31 | IC23.13 121.28,46.82 113.03,55.08 85.72,55.08 84.45,56.35 73.66,56.35 72.39,55.08 72.39,51.91 67.94,51.91 67.31,52.54 67.31,55.71 65.4,55.71 64.13,54.45 IC21.20
D3
  Top 0.254: 125.73,58.89 124.45,60.16 IC23.15 | 125.73,58.89 125.73,43.65 124.45,42.38 IC22.15 | 125.73,58.89 125.73,79.21 124.45,80.48 IC29.15
  Bottom 0.254: IC21.19 65.4,53.17 64.13,51.91 52.7,51.91 41.9,62.7 41.9,80.48 40.63,80.48 IC17.30 41.27,82.39 46.98,88.1 115.56,88.1 120.65,83.02 120.65,79.84 122.55,79.84 123.82,81.11 IC29.15 | IC24.30 36.82,30.95 38.09,29.68 66.67,29.68 67.94,30.95 109.22,30.95 118.11,39.84 118.11,43.02 122.55,43.02 123.82,41.74 IC22.15
D4  (via drill 0.61)
  Top 0.254: IC22.16 121.92,42.38 120.65,43.65 120.65,48.09 121.92,49.37 121.92,60.16 IC23.16 121.92,62.7 120.65,63.97 120.65,79.21 121.92,80.48 IC29.16 | v53.97,46.82 77.47,46.82 77.47,55.08 76.83,55.71 74.93,55.71 | 74.93,55.71 74.93,52.54 74.29,51.91 68.58,51.91 68.58,52.54 IC21.18 | 64.77,69.05 67.31,69.05 69.21,67.14 74.93,67.14 74.93,55.71 | 64.77,69.05 60.95,69.05 54.6,75.4 54.6,83.66 45.08,83.66 43.81,82.39 IC17.29 | 64.77,69.05 v64.77,70.32
  Bottom 0.254: v53.97,46.82 40.63,46.82 40.63,45.55 41.9,44.28 41.9,37.3 36.82,32.22 33.65,32.22 33.65,30.31 34.92,29.04 IC24.29 | v64.77,70.32 65.4,69.69 120.65,69.69 120.65,65.24 121.28,64.61 121.92,64.61 121.92,62.7 IC23.16
D5
  Top 0.254: IC29.17 119.38,80.48 118.11,79.21 118.11,63.97 119.38,62.7 IC23.17 119.38,60.16 119.38,49.37 118.11,48.09 118.11,43.65 119.38,42.38 IC22.17
  Bottom 0.254: IC24.28 36.82,25.87 40,29.04 67.31,29.04 68.58,30.31 109.85,30.31 119.38,39.84 IC22.17 | IC21.17 71.12,55.08 71.12,58.25 116.2,58.25 118.74,60.8 IC23.17 | IC17.28 46.35,82.39 51.43,87.47 113.66,87.47 118.74,82.39 IC29.17
D6  (via drill 0.61)
  Top 0.254: IC22.18 116.84,42.38 115.56,43.65 115.56,57.62 116.84,58.89 116.84,60.16 IC23.18 116.84,62.7 115.56,63.97 115.56,79.21 116.84,80.48 IC29.18 | 44.45,79.84 47.62,79.84 47.62,81.11 IC17.27 | 44.45,79.84 42.54,79.84 41.9,80.48 41.9,83.66 32.38,83.66 31.75,83.02 31.75,80.48 34.28,77.94 34.28,65.24 33.02,63.97 33.02,25.87 34.92,23.96 IC24.27 | 71.75,58.89 68.58,62.06 44.45,62.06 44.45,79.84 | 71.75,58.89 73.66,56.98 73.66,55.08 IC21.16 | 71.75,58.89 v73.02,60.16
  Bottom 0.254: v73.02,60.16 73.66,59.52 105.41,59.52 105.41,67.78 106.04,68.41 118.11,68.41 118.11,65.24 117.47,64.61 116.84,64.61 116.84,62.7 IC23.18
D7
  Top 0.254: IC24.26 36.19,21.42 42.54,27.77 42.54,40.48 44.45,42.38 44.45,49.37 45.08,50 75.56,50 75.56,53.17 IC21.15 | IC22.19 114.3,42.38 113.03,43.65 113.03,57.62 114.3,58.89 114.3,60.16 IC23.19 114.3,62.7 113.03,63.97 113.03,79.21 114.3,80.48 IC29.19
  Bottom 0.254: IC17.26 51.43,82.39 55.88,86.83 109.22,86.83 113.66,82.39 IC29.19 | IC21.15 76.83,54.45 78.1,55.71 83.81,55.71 91.44,48.09 114.93,48.09 115.56,47.46 115.56,43.65 114.3,42.38 IC22.19
E
  Top 0.254: IC24.25 34.28,18.25 26.67,25.87 26.67,76.67 22.86,80.48 IC17.37 22.86,83.02 22.86,83.66 29.21,83.66 31.11,85.56 31.11,86.83 73.66,86.83 74.93,85.56 74.93,70.32 76.83,68.41 76.83,67.78 77.47,67.14 77.47,56.35 78.73,55.08 IC21.14
  Bottom 0.254: IC18.10 115.56,10.63 111.76,6.82 89.53,6.82 84.45,1.74 48.89,1.74 37.46,13.17 37.46,14.44 34.28,14.44 33.65,15.08 33.65,18.25 34.28,18.25 IC24.25
EP2\
  Top 0.254: IC28.9 86.99,84.92 106.68,84.92 106.68,83.02 IC29.22
  Bottom 0.254: IC29.22 107.31,81.11 108.58,79.84 109.85,79.84 111.12,81.11 IC29.20
GND
  Top 0.508: IC28.8 86.99,76.67 88.26,76.67 BYP29.2 | IC17.21 64.13,81.11 65.4,79.84 65.4,79.21 BYP28.2 | BYP23.2 86.36,56.98 87.62,58.25 87.62,62.7 86.99,63.34 IC19.8 | R13.1 41.9,56.98 46.98,51.91 55.24,51.91 55.24,53.17 IC21.23 | IC25.19 16.51,53.81 19.05,56.35 IC24.1 20.32,56.98 20.32,58.25 BYP24.2 19.68,58.89 14.6,63.97 14.6,64.61 | C1.1 5.08,79.84 5.08,81.11 C2.2 | BYP25.2 9.52,58.89 5.08,58.89 5.08,60.16 JP4.1 | 14.6,64.61 10.15,60.16 10.15,59.52 BYP25.2 | 14.6,64.61 15.23,65.24 IC17.1 | CORE-IO.10 5.71,33.49 6.34,33.49 IC25.10 8.25,32.85 8.25,32.22 9.52,30.95 BYP26.2 | 12.69,27.14 10.15,29.68 10.15,30.31 BYP26.2 | 12.69,27.14 13.96,25.87 IC26.19 | 12.69,27.14 12.69,10.63 8.25,6.18 IC26.10 8.88,5.55 13.33,5.55 13.33,4.92 15.23,3.01 33.65,3.01 33.65,8.73 34.28,9.36 38.73,9.36 38.73,13.17 X1.G2 | BYP25.2 10.15,58.25 10.15,31.58 BYP26.2 | C6.2 91.44,6.18 91.44,7.46 C4.2 | BYP18.2 107.31,5.55 107.95,5.55 IC18.7 109.22,4.92 109.22,4.28 JP1.1 | 99.06,15.08 106.68,22.7 BYP17.2 | 99.06,15.08 94.61,10.63 C5.2 | BYP21.2 50.79,43.02 53.34,40.48 53.34,39.84 IC21.1 53.34,37.3 50.79,34.76 IC20.15 50.79,32.22 52.06,30.95 52.06,23.96 51.43,23.33 C11.2 50.79,22.7 50.79,21.42 C7.2 | IC27.7 74.93,8.09 67.31,8.09 67.31,12.54 X1.G1 63.49,14.44 48.25,14.44 48.25,15.08 X1.5 48.25,16.34 48.25,20.15 BYP20.2 | 99.06,15.08 88.9,25.23 88.9,35.39 BYP22.2
  Bottom 0.508: IC28.8 86.36,77.94 83.81,80.48 67.94,80.48 66.67,79.21 BYP28.2 66.04,78.58 60.95,73.5 60.95,69.69 48.89,69.69 46.98,67.78 46.98,63.97 66.04,63.97 | 124.45,56.35 124.45,59.52 123.82,59.52 123.19,60.16 123.19,65.88 123.82,65.88 IC29.14 | 124.45,56.35 124.45,47.46 IC23.14 123.82,45.55 121.92,43.65 116.84,43.65 115.56,42.38 115.56,38.57 92.07,38.57 89.53,36.03 BYP22.2 88.26,36.03 87.62,35.39 65.4,35.39 64.13,34.12 IC20.10 62.86,32.85 61.59,31.58 52.7,31.58 51.43,32.85 IC20.15 | 63.49,61.43 66.04,63.97 | 63.49,61.43 56.51,54.45 IC21.23 | 66.04,63.97 66.04,65.88 BYP19.2 | 63.49,61.43 83.81,61.43 85.72,63.34 IC19.8 | 124.45,56.35 86.99,56.35 BYP23.2 | C1.1 5.08,78.58 15.23,68.41 15.23,67.78 IC17.1 | IC26.10 8.88,5.55 10.15,6.82 20.32,6.82 JP3.1 | CORE-IO.11 3.17,30.95 5.08,32.85 CORE-IO.10 | C5.2 93.98,10 92.07,8.09 C4.2 | BYP18.2 106.04,5.55 104.77,5.55 102.23,3.01 C3.2 100.96,3.01 94.61,3.01 92.07,5.55 C6.2 | BYP27.2 79.37,25.87 81.28,27.77 104.77,27.77 105.41,27.14 105.41,23.96 106.68,23.96 BYP17.2 107.31,23.33 121.92,23.33 123.82,25.23 IC22.14 | BYP20.2 48.89,20.79 50.16,20.79 C7.2 | X1.5 47.62,15.71 42.54,15.71 X1.G2
HLT\
  Bottom 0.254: R5.1 10.15,68.41 13.96,64.61 15.87,64.61 17.14,65.88 IC17.2
IO-E\  (1 unrouted)
IO-F\
  Top 0.254: IC21.9 73.66,39.84 83.81,50 83.81,62.7 IC19.7
IRQ\
  Top 0.254: R7.1 37.46,48.73 36.82,48.73 IC24.37 34.92,49.37 34.92,50.63 IC24.38
  Bottom 0.254: IC17.4 23.49,65.88 34.28,55.08 36.82,55.08 37.46,54.45 37.46,51.91 36.19,51.91 IC24.38
MR
  Top 0.254: R8.1 13.33,69.05 20.32,69.05 20.32,67.78 IC17.3
N$3
  Top 0.254: Q1.1 5.08,74.77 8.88,78.58 8.88,79.84 10.15,81.11 C2.1
  Bottom 0.254: IC17.39 17.14,81.11 15.87,79.84 12.69,79.84 10.79,81.75 C2.1
N$4
  Top 0.254: Q1.2 5.08,69.69 8.88,73.5 8.88,77.3 10.15,78.58 C1.2
  Bottom 0.254: IC17.38 19.68,81.11 17.78,79.21 10.79,79.21 C1.2
N$5
  Top 0.254: IC25.18 16.51,51.27 19.05,53.81 IC24.2
N$6
  Top 0.254: IC18.5 108.58,11.27 108.58,12.54 IC18.4 108.58,13.81 108.58,15.08 IC18.3
N$21
  Top 0.254: IC18.1 107.95,20.79 107.31,20.79 R1.1 106.68,20.15 105.41,18.88 105.41,17.61 101.59,13.81 C3.1
N$22
  Top 0.254: IC18.2 107.95,18.25 107.31,18.25 R2.1 106.68,17.61 105.41,16.34 105.41,4.28 106.04,3.64 JP1.2
N$23
  Top 0.254: IC21.3 59.05,37.94 60.32,37.94 IC21.4 60.95,37.3 60.95,36.03 67.94,36.03 69.84,34.12 69.84,18.25 74.93,13.17 IC27.5
N$24
  Top 0.254: IC26.18 16.51,23.33 17.78,24.6 17.78,30.95 19.68,32.85 IC24.10
N$25
  Bottom 0.254: IC26.17 15.87,21.42 17.14,22.7 17.14,30.95 19.05,30.95 IC24.11
N$27
  Top 0.254: IC27.2 75.56,20.15 74.29,18.88 R11.A | IC27.6 74.93,10.63 71.75,10.63 R11.S
  Bottom 0.254: C6.1 85.72,5.55 84.45,6.82 81.28,6.82 77.47,10.63 IC27.6 | R11.A 73.66,16.98 73.66,11.9 71.12,11.9 R11.S
N$28
  Top 0.254: IC27.1 76.83,22.7 78.1,21.42 78.1,6.82 76.83,5.55 R9.1
  Bottom 0.254: R9.1 76.83,5.55 79.37,3.01 83.18,3.01 R10.2
N$94
  Top 0.254: IC26.16 15.87,18.88 18.41,21.42 18.41,26.5 19.68,27.77 IC24.12
N$124
  Bottom 0.254: IC26.15 15.87,16.34 17.78,18.25 17.78,25.87 19.05,25.87 IC24.13
N$125
  Bottom 0.254: IC26.14 15.87,13.81 18.41,16.34 18.41,23.33 19.05,23.33 IC24.14
N$126
  Bottom 0.254: IC26.13 16.51,10.63 17.78,11.9 21.59,11.9 22.22,12.54 22.22,20.15 20.95,20.15 IC24.15
N$127
  Top 0.254: IC26.12 14.6,8.73 13.33,10 13.33,16.34 13.96,16.98 19.05,16.98 19.05,18.25 IC24.16
N$128
  Top 0.254: IC26.11 15.87,4.92 17.14,3.64 24.12,3.64 24.12,11.9 20.95,15.08 IC24.17
N$129
  Top 0.254: IC25.17 16.51,48.73 19.05,51.27 IC24.3
N$130
  Top 0.254: IC25.16 16.51,46.19 19.05,48.73 IC24.4
N$131
  Top 0.254: IC25.15 16.51,43.65 19.05,46.19 IC24.5
N$132
  Top 0.254: IC25.14 16.51,41.11 19.05,43.65 IC24.6
N$133
  Top 0.254: IC25.13 16.51,38.57 19.05,41.11 IC24.7
N$134
  Top 0.254: IC25.12 16.51,36.03 19.05,38.57 IC24.8
N$135
  Top 0.254: IC25.11 16.51,33.49 19.05,36.03 IC24.9
N$136
  Bottom 0.254: IC24.19 19.05,10.63 17.78,9.36 13.96,9.36 9.52,13.81 9.52,27.77 8.25,27.77 IC26.1
N$137
  Bottom 0.254: IC24.39 34.28,53.81 33.02,55.08 10.15,55.08 8.88,56.35 IC25.1
N$138  (via drill 0.61)
  Top 0.254: v31.11,27.77 v31.11,59.52 | v45.71,23.33 46.35,22.7 46.35,13.81 56.51,3.64 74.93,3.64 75.56,4.28 81.91,4.28 81.91,8.73 83.18,10 IC27.9
  Bottom 0.254: v31.11,59.52 34.28,56.35 IC24.40 | v31.11,27.77 34.28,24.6 44.45,24.6 v45.71,23.33
N$140
  Top 0.254: IC27.8 85.09,8.09 85.72,8.09 C4.1 | IC27.12 84.45,17.61 90.8,11.27 90.8,10.63 R4.1
  Bottom 0.254: R4.1 90.8,10.63 88.26,8.09 86.99,8.09 C4.1
N$141
  Top 0.254: R4.2 90.8,18.25 89.53,18.25 R3.1 88.9,18.88 88.9,20.79 85.09,20.79 IC27.13
N$142
  Bottom 0.254: IC27.11 85.09,15.71 93.34,15.71 C5.1
N$143
  Bottom 0.254: R10.1 75.56,3.01 74.29,4.28 73.66,4.28 R11.E
N$144
  Bottom 0.254: X1.4 50.79,15.08 51.43,14.44 56.51,14.44 57.14,13.81 X1.6
N$145
  Top 0.254: X1.8 52.7,13.17 53.97,13.17 X1.7
N$147  (via drill 0.61)
  Top 0.254: IC18.12 116.2,16.34 116.2,17.61 IC18.13 116.2,18.88 113.03,22.06 v113.03,28.41 | v77.47,28.41 69.84,36.03 69.84,36.66 65.4,36.66 64.13,37.94 IC21.5
  Bottom 0.254: v77.47,28.41 v113.03,28.41
N$148
  Top 0.254: LED1.K 119.38,11.27 118.11,12.54 118.11,13.17 IC18.11
N$149
  Bottom 0.254: R12.1 86.99,18.25 88.26,16.98 110.48,16.98 115.56,11.9 120.01,11.9 121.28,10.63 LED1.A
N$150
  Top 0.254: R13.2 50.16,57.62 52.7,57.62 JP2.1 53.34,56.35 53.34,55.08 IC21.24
N$151
  Top 0.254: IC28.1 69.21,76.03 70.48,74.77 72.39,74.77 72.39,81.75 71.12,83.02 IC28.15
  Bottom 0.254: IC18.8 118.11,5.55 121.28,8.73 123.19,8.73 125.73,11.27 125.73,79.21 93.98,79.21 92.7,80.48 92.7,83.66 88.26,83.66 86.99,82.39 73.02,82.39 71.75,83.66 IC28.15
N$153
  Top 0.254: IC20.7 64.13,25.23 65.4,25.23 IC20.8
N$154
  Bottom 0.254: IC27.3 76.83,18.88 78.1,20.15 78.1,22.06 57.78,22.06 56.51,20.79 C7.1
N$155
  Top 0.254: IC20.5 59.05,26.5 64.13,31.58 67.94,31.58 67.94,33.49 C9.2
N$156
  Bottom 0.254: IC20.4 56.51,26.5 58.41,28.41 67.94,28.41 C9.1
N$157
  Top 0.254: IC20.3 53.34,24.6 52.7,23.96 52.7,20.79 51.43,19.52 49.52,19.52 49.52,27.77 46.35,30.95 C8.2
N$158
  Top 0.254: C8.1 46.35,25.87 47.62,25.87 IC20.1
N$159
  Bottom 0.254: C11.1 56.51,23.33 57.14,23.96 59.05,23.96 60.32,25.23 IC20.6
N$160
  Bottom 0.254: C10.2 48.89,23.33 50.16,24.6 50.79,24.6 IC20.2
NMI\  (via drill 0.61)
  Top 0.254: v48.89,38.57 44.45,34.12 44.45,19.52 34.28,19.52 32.38,21.42 32.38,60.8 27.94,65.24 IC17.6
  Bottom 0.254: 70.48,40.48 73.66,43.65 85.72,43.65 R6.1 | 70.48,40.48 69.21,39.2 IC21.7 | v48.89,38.57 50.79,40.48 70.48,40.48
PIA-A0
  Bottom 0.254: IC25.2 6.98,53.17 2.54,48.73 2.54,44.28 CORE-IO.1
PIA-A1
  Bottom 0.254: IC25.3 6.98,50.63 5.08,48.73 5.08,44.28 CORE-IO.2
PIA-A2
  Top 0.254: IC25.4 6.34,48.73 1.27,48.73 1.27,43.02 2.54,41.74 CORE-IO.3
PIA-A3
  Top 0.254: IC25.5 6.34,46.19 3.81,46.19 3.81,43.02 5.08,41.74 CORE-IO.4
PIA-A4
  Bottom 0.254: IC25.6 8.25,43.02 9.52,41.74 9.52,39.84 4.44,39.84 3.17,38.57 CORE-IO.5
PIA-A5
  Top 0.254: IC25.7 6.98,40.48 5.71,39.2 5.71,38.57 CORE-IO.6
PIA-A6
  Bottom 0.254: IC25.8 6.98,37.94 6.34,37.3 4.44,37.3 3.17,36.03 CORE-IO.7
PIA-A7
  Top 0.254: IC25.9 6.34,36.03 5.71,36.03 CORE-IO.8
PIA-B0
  Bottom 0.254: IC26.2 6.98,26.5 6.34,27.14 4.44,27.14 3.17,28.41 CORE-IO.13
PIA-B1
  Bottom 0.254: IC26.3 6.98,23.96 6.34,24.6 1.9,24.6 1.27,25.23 1.27,29.68 3.17,29.68 4.44,28.41 CORE-IO.14
PIA-B2
  Top 0.254: IC26.4 6.34,20.79 6.34,21.42 5.71,22.06 4.44,22.06 3.81,22.7 3.81,23.96 2.54,25.23 CORE-IO.15
PIA-B3
  Top 0.254: IC26.5 8.25,18.88 9.52,20.15 9.52,23.96 8.88,24.6 5.08,24.6 5.08,25.23 CORE-IO.16
PIA-B4
  Top 0.254: IC26.6 6.34,15.71 3.81,15.71 3.81,21.42 2.54,22.7 CORE-IO.17
PIA-B5
  Bottom 0.254: IC26.7 6.98,13.81 3.81,16.98 3.81,23.33 4.44,23.33 CORE-IO.18
PIA-B6
  Top 0.254: IC26.8 6.98,11.27 2.54,15.71 2.54,20.15 CORE-IO.19
PIA-B7
  Top 0.254: IC26.9 8.25,8.73 9.52,10 9.52,16.34 8.88,16.98 5.08,16.98 5.08,20.15 CORE-IO.20
R/W\
  Top 0.254: 88.9,37.94 87.62,36.66 87.62,25.23 92.7,20.15 92.7,1.74 57.14,1.74 50.79,8.09 36.82,8.09 IC24.21 | 88.9,37.94 93.34,37.94 93.34,40.48 IC22.27 | 88.9,37.94 85.09,41.74 85.09,65.88 83.18,65.88 82.55,65.24 82.55,56.35 81.28,55.08 IC21.13
  Bottom 0.254: IC17.34 31.11,82.39 33.02,84.29 38.09,84.29 39.36,83.02 39.36,60.8 42.54,60.8 52.06,51.27 78.73,51.27 80.64,53.17 IC21.13
RST\  (via drill 0.61)
  Top 0.254: v38.09,44.92 37.46,44.28 37.46,43.02 36.19,41.74 IC24.34 | IC17.40 15.23,80.48 24.12,71.59 v24.12,53.81 24.12,16.98 36.82,16.98 37.46,17.61 42.54,17.61 43.81,16.34 43.81,15.71 v45.08,14.44
  Bottom 0.254: v24.12,53.81 33.02,44.92 v38.09,44.92 | v45.08,14.44 50.79,8.73 72.39,8.73 72.39,9.36 74.93,11.9 94.61,11.9 97.15,9.36 106.68,9.36 107.95,8.09 IC18.6
RX
  Top 0.254: IC20.12 58.41,34.76 55.88,37.3 IC21.2
RXD
  Top 0.254: IC20.13 55.88,32.22 54.6,30.95 54.6,17.61 53.34,16.34 X1.3
TX
  Bottom 0.254: IC20.11 61.59,34.12 65.4,37.94 IC21.6
TXD
  Top 0.254: IC20.14 53.97,34.12 55.24,35.39 56.51,35.39 57.14,34.76 57.14,16.98 56.51,16.34 X1.2
VCC  (via drill 0.61)
  Top 0.508: 67.31,84.29 67.94,84.29 IC28.16 | 67.31,84.29 66.67,84.29 BYP28.1 | 67.31,84.29 67.31,74.13 68.58,72.86 IC19.16 | IC29.28 91.44,80.48 91.44,67.78 IC29.1 91.44,65.24 91.44,62.7 IC23.28 91.44,60.16 91.44,47.46 IC23.1 91.44,44.92 91.44,42.38 IC22.28 | 88.26,10.63 88.26,6.82 85.72,6.82 84.45,5.55 R9.2 | 88.26,10.63 R3.2 88.26,10.63 | 88.26,10.63 86.99,10.63 R12.2 86.36,11.27 85.09,12.54 85.09,13.17 IC27.10 | R2.2 99.06,18.88 99.06,20.15 R1.2 99.69,20.79 101.59,22.7 BYP17.1 | IC27.14 83.81,23.96 83.81,25.23 BYP27.1 83.81,26.5 81.91,28.41 | 81.91,28.41 81.28,29.04 81.28,37.3 IC21.12 81.28,39.84 81.28,40.48 78.1,40.48 76.83,39.2 IC21.10 | 81.91,28.41 81.91,15.08 83.18,13.81 IC27.10 | R8.2 12.06,76.67 10.79,76.67 R5.2 10.15,76.03 9.52,75.4 9.52,70.32 7.62,68.41 7.62,62.7 JP4.2 | IC17.36 26.03,81.11 27.3,81.11 IC17.35 27.94,80.48 27.94,72.86 33.02,67.78 IC17.8 | IC26.20 15.23,29.04 15.23,30.31 BYP26.1 14.6,30.95 13.33,32.22 13.33,54.45 14.6,55.71 IC25.20 15.23,56.98 15.23,58.25 BYP25.1 | CORE-IO.12 4.44,30.95 2.54,32.85 CORE-IO.9 | IC20.16 48.25,34.76 50.79,37.3 50.79,37.94 BYP21.1 50.79,39.2 49.52,40.48 | 48.89,44.92 49.52,44.28 49.52,40.48 | 48.89,44.92 45.71,48.09 R7.2 | v47.62,53.17 47.62,60.16 53.97,60.16 54.6,59.52 54.6,58.89 55.24,58.25 JP2.2 | R14.2 17.78,6.18 19.05,7.46 19.05,8.09 IC24.20 | BYP20.1 43.17,21.42 43.17,22.7 C10.1 43.81,23.33 43.81,40.48 49.52,40.48 | IC24.22 36.19,11.27 37.46,12.54 37.46,13.81 36.19,15.08 IC24.24 | 48.89,44.92 64.77,44.92 69.84,39.84 69.84,37.94 80.01,27.77 80.01,15.71 82.55,13.17 IC27.10
  Bottom 0.508: BYP19.1 66.67,71.59 67.94,71.59 IC19.16 | IC29.28 90.8,81.75 89.53,81.75 BYP29.1 88.26,81.75 71.12,81.75 69.21,83.66 IC28.16 | BYP23.1 86.99,61.43 90.8,61.43 IC23.28 92.07,60.8 93.34,60.8 IC23.27 | 78.73,14.44 80.01,13.17 82.55,13.17 IC27.10 | 78.73,14.44 77.47,15.71 IC27.4 | 78.73,14.44 102.23,14.44 106.04,10.63 BYP18.1 | IC18.14 115.56,20.79 114.3,19.52 100.96,19.52 99.69,20.79 R1.2 | IC21.8 71.75,39.2 73.02,40.48 74.29,40.48 75.56,39.2 IC21.10 | IC21.12 81.91,39.2 83.81,41.11 88.26,41.11 BYP22.1 89.53,41.11 90.8,41.11 IC22.28 | R6.2 86.36,50.63 90.17,46.82 90.8,46.82 IC23.1 | BYP17.1 100.96,23.33 85.09,23.33 IC27.14 | R8.2 13.33,76.67 15.23,78.58 22.22,78.58 24.76,81.11 IC17.36 | IC26.20 13.96,28.41 12.69,29.68 6.98,29.68 5.71,30.95 CORE-IO.12 | 17.78,57.62 23.49,57.62 24.76,58.89 BYP24.1 | 17.78,57.62 16.51,56.35 IC25.20 | 17.78,57.62 7.62,57.62 7.62,60.16 JP4.2 | v47.62,53.17 47.62,49.37 45.71,49.37 R7.2 | 41.27,19.52 37.46,15.71 36.82,15.71 IC24.24 | 41.27,19.52 42.54,20.79 BYP20.1 | IC24.20 21.59,8.09 24.12,10.63 34.28,10.63 IC24.22 | 41.27,19.52 34.28,19.52 21.59,32.22 17.14,32.22 15.87,30.95 BYP26.1
VMA
  Bottom 0.254: IC18.9 118.11,8.09 119.38,9.36 122.55,9.36 123.19,10 123.19,22.06 80.01,22.06 77.47,24.6 67.31,24.6 65.4,22.7 57.14,22.7 56.51,22.06 34.28,22.06 22.22,34.12 22.22,52.54 11.42,52.54 8.88,55.08 6.34,55.08 3.81,57.62 3.81,63.97 20.32,63.97 21.59,65.24 21.59,68.41 23.49,68.41 24.76,67.14 IC17.5

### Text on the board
Top: Component Side
Bottom: Solder side | PA8PDP/VRS
tPlace: RealConsole CORE - Rev.1 | +
tValues: - | +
